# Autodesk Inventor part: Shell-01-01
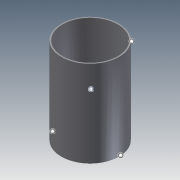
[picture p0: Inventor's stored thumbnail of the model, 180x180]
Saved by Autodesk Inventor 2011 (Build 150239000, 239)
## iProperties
Created: 2010-06
Part Number: Shell-01-01
Document SubType Name: Modeling
Designer: mklassen
Density: 1 g/cm^3
OD: 36.000 in
THK: 0.625 in
LEN: 6.000 ft
SKVOFS: 6.000 in
Author: mklassen
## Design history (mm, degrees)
sketch "skShell"
  geometry: C1 r 457.2 at (0, 0); C2 r 441.325 at (0, 0); 1 further point
  constraints: 2 centre point, 1 coincident
  dimensions: "d0" = 914.4 diameter of C1 (derived); "d1" = 15.875 radial gap between concentric circles of C2 C1 (derived)
extrude "Shell" new body sketch "skShell" stored distance "d2" = 1828.8 (derived); taper "d3" = 0 deg
body "Solid1"
other parameters: "d4" = 0, "d5" = 0, "d6" = 0, "d7" = 0, "d8" = 0, "SKVOFS" = 152.4 [user parameter; used in 1 equation term], "d9" = -152.4 (= -SKVOFS)
